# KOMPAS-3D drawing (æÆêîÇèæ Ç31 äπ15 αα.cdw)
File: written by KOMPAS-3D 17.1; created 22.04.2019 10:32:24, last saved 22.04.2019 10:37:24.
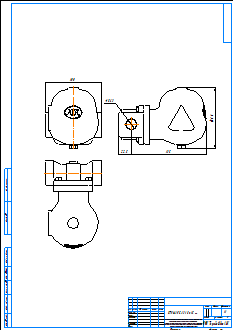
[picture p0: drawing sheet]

Sheet 1: A2, portrait

Title block, sheet 1: name: СТИМАКС А31 Ду15 рр; material: Внимание! Данный продукт является объектом авторского права ООО «Торговый Дом АДЛ». / Запрещается изменение, копирование, распространение / (в том числе путем копирования на другие сайты и ресурсы в Интернете) / или любое иное использование информации и объектов без предварительного / согласия правообладателя (ООО «Торговый Дом АДЛ»).; sheets: 1; organisation: ООО "Торговый дом АДЛ"; sheet format: A2; stored path: \\adlc.lan\data\АДЛ_ПКД\3D-модели\ADL production\Конденсатоотводчики СТИМАКС\Поплавковые\Серия А31\KOMPAS 2D\СТИМАКС А31 Ду15 рр.cdw

Views: Вид 1, Проекционный вид 2, Проекционный вид 3
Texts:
  user
Dimensions and other numbers on the sheet: 100; 18,63; 22,5; 135; 109,3; 1:1; 1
